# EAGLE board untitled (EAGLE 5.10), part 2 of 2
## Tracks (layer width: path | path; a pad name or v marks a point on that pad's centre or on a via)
+5V  (via drill 0.6 pad 1.78)  (4 unrouted)
  Top 0.254: v109.6,55.4 109.6,47.6
  Bottom 0.406: 126.8,57.4 126.8,53
  Bottom 0.61: 135.8,47.66 135.8,48.6 134.8,49.6 126.8,49.6 | 126.8,49.6 125.6,49.6 | 126.8,53 126.8,50.8 | 126.8,50.8 126.8,49.6 | 126.8,50.8 125.6,49.6 | 126.8,50.8 127.8,49.8 127.4,49.8 127.2,50 126.4,50 | 125.6,49.6 110.8,49.6 109.6,48.4
  Bottom 0.813: 135.8,47.66 U1.7 135.8,47.52 135.8,44 138.8,41 141.4,41 144.2,38.2 144.2,35.6 143.3,34.7 141.2,34.7 | 109.6,48.4 109.6,48 | L1.1 124.59,59.61 126.8,57.4 | 115.8,29.6 109.2,36.2 109.2,47.2 109.6,47.6 | 115.8,29.6 116.1,29.3 | STER..10 129.14,38.86 132.4,35.6 136,35.6 | 136,35.6 140.3,35.6 141.2,34.7 | 117.8,28.4 118.6,27.6 118.4,27.6 | WYS..1 134.8,10.59 134.8,16.2 141.7,23.1 | 116.1,29.3 116.2,29.2 | 116.2,29.2 117.8,27.6 118.4,27.6 | P1*.A 116.1,28.38 116.1,29.3 | R6*.2 118.4,28.6 117.8,29.2 116.2,29.2 | 117,28.8 117.6,28.8 118,28.4 117,28.4 115.8,29.6 | 115.8,29.6 117.4,29.6 118.8,28.2 118.8,28 118.4,27.6 | 118.4,27.6 117,27.6 116.4,28.2 | 145.83,26.97 146.6,27.75 146.6,29.8 144.4,32 | 145.83,26.97 PIEZO1.+ | 141.2,34.7 143,33.4 | 143,33.4 143.2,33.2 | 143.6,24.6 145.83,26.83 145.83,26.97 | 142.8,23.8 143.6,24.6 | 143,33.4 143,34.6 | 143,33.4 143,34.2 144.2,35.4 144.2,32.2 144.4,32 | 143.2,33.2 144.4,32 | 143.2,33.2 143.6,33.2 143.8,33.4 143.8,33.8 143.6,34 | 136,35.6 138,33.6 138,31.2 138.8,30.4 140.8,30.4 142.8,28.4 142.8,23.8 | 142.8,23.8 142.8,24 145.4,26.6 | 145.2,26.6 145.2,27.2 146,28 146,29.6 140.6,35 137.4,35 137.4,34.8 138.4,33.8 138.4,34.2 138.6,34.4 144,34.4 146.6,31.8 148.2,31.8 151.2,28.8 151.2,24.2 150.12,23.12 149.8,23.12 | 149.8,23.12 144.2,23.12 144.2,23.6 145,24.4 | 150.4,25.8 150.2,25.6 150.2,24 149.8,23.6 149.8,23.12 | 143.6,24.6 143.2,24.6 141.7,23.1 | 141.7,23.1 145.2,23.1 | 141.7,23.1 142.2,23.6 143.3,23.6 143.4,23.7 146.1,23.7 | 51.6,100.4 52.8,101.6 61.4,101.6 60.6,100.8 52.6,100.8 52.8,101 61.6,101 62.6,102 62.6,102.8 65.2,100.2 67.6,100.2 | 64.2,100.2 63,101.4 63,101.8 62.2,101 62.2,100.8 62.4,101 63,101
  Bottom 1.016: 98.2,134 98,133.6 98.4,134 103.8,134 108.4,138.6 108.4,144.2 109.2,145 121.6,145 124.06,142.54 124.06,142 U4.1 | v109.6,55.4 109.4,55.8 110.4,56.8 110.4,71.4 81.4,100.2 67.6,100.2 64.2,100.2 50.4,100.2 35,100.2 25.8,109.4 25.8,142.2 31.8,148.2 42.2,148.2 52.4,158.4 70.6,158.4 71.8,157.2 71.8,148.2 76.4,143.6 83.4,143.6 86.2,140.8 88.6,140.8 89.6,139.8 89.6,133.6 | 60.74,110.26 61,110 | 60.74,110.26 7805.OUT | 60.2,101.56 C5.2 | 60.2,101.56 60.64,101.56 C13.+ | 60.74,110.26 61.14,110.26 62.6,108.8 62.6,102.8 62.6,102.4 61.8,101.6 61.4,101.6 60.24,101.6 60.2,101.56
  Bottom 2.184: 143.6,24.6 144.4,24.8 145,24.8 | 146.2,24.6 145.2,25.4 145,24.4 145.8,25.2 147,25.2 147.8,24.8 148.6,25.2 149.8,26.4 147.2,24.4 147,24.2 148.8,24.2 | 150.4,25.8 150.4,28.6 148.4,28.6 146.6,26.8 148,26.8 148.6,26.2 148.6,27 148.8,27.2 148.8,29.8 147.8,30.8 147.8,30.4 147,29.6 147,30.2 144.8,32.4 142,32.4 141,33.4 139,33.4 139,31.8 139.4,31.4 142.6,31.4 144.8,29.2 144.8,28.4 144.6,28.2 144.4,28.2 | 144.4,28.2 142.2,30.4 | 144.4,28.2 144.8,27.8 144.8,27.2 143.8,26.2 143.8,27.6
+12V  (via drill 0.5 pad 3.81, 0.6 pad 2.18, 0.6 pad 2.54)  (1 unrouted)
  Top 0.254: v77.5,150.3 v66,150.3
  Bottom 0.406: 142.6,123.4 142.2,123.4 142.2,123.6 | 139.6,121.6 139.4,121.6 139.4,121.4 | 143.4,122.2 142.6,122.2 | 144.2,121.6 144.4,121.6 144.4,121.4
  Bottom 1.016: 110.5,164 112.1,165.6 112.1,169.8 113,170.5 v113,170.6 D2.C 113.69,170.69 117.4,174.4 117.4,186.8 116,188.2 v115.2,188.2 PK2.2 | 110.5,164 103.5,164 100,160.5 91,160.5 85,154.5 85,149.5 83.5,148 79.1,148 77.5,149.6 v77.5,150.3 77.5,157 82,161.5 82,164 80,166 76,166 71.5,161.5 58,161.5 56.5,163 56.5,169.5 55,171 47,171 39.7,163.7 39.7,163.49 D1.C 39.4,159.8 38,158.4 28,158.4 26.79,159.61 PK1.1 | 110.5,164 110.5,159.4 109,157.9 103.5,157.9 101.4,155.8 97,155.8 96.5,155.3 | 741.7 125.6,107.64 125.6,108.3 128.5,111.2 128.5,116.5 130,118 136,118 139.4,121.4 | v151.4,88.6 148.8,86 138.4,86 136.8,84.4 129,84.4 127.97,83.37 U741.7 128,82.26 128,79.6 | 156.6,89.2 156.2,88.8 | 156.6,89.2 156.8,89.4 | X8.2 X9.2 X10.2 138.2,78 136.6,79.6 128,79.6 | D3.C 126.79,78.19 128,79.4 128,79.6 | 143.4,125.4 143.4,142.4 139.2,146.6 130,146.6 128,148.6 122.8,148.6 121.4,147.2 109,147.2 106.8,145 106.8,139.2 103.8,136.2 95.6,136.2 | 143.4,125.4 143.4,122.2 143.4,122 | 144.4,121.4 148.4,117.4 156.6,117.4 158,116 158,90.6 156.6,89.2 | 96.5,155.3 95.7,154.5 | 143.4,125.4 139.6,121.6 | 143.4,125.4 143.4,122.4 144.2,121.6 | 142.6,122.2 142.6,123.4 142.8,123.6 | 142.2,123.6 142.8,124.2 | 110.21,140.81 LM358.8 110.2,138 106.2,134 106.2,128 104.8,126.6 104.8,109.4 103.4,108 100.2,108 99,109.2 99,112.8 101.2,115 101.2,118.8 98.8,121.2 98.8,127.4 95.6,130.6 95.6,136.2 | 95.6,136.2 95.6,154.4 96.5,155.3 | 66.88,150.32 66.68,150.22 66.66,150.2 66,150.2 | 60.84,125.56 7812.OUT | 60.84,125.56 61.24,125.56 | v66,150.3 66,150.2 | 60.84,125.56 61.64,125.56 63,124.2 63,119 61.8,117.8 60.32,117.8 C14.+ 60.12,118 54.6,118 v53.8,117.2 C9.1 55.16,115.8 62.8,115.8 64.8,117.8 64.8,129.4 68.2,132.8 68.2,143.6 66,145.8 66,150.2
-5V  (via drill 0.6 pad 2.18)  (1 unrouted)
  Top 0.254: v95.4,93.6 v114,93.6
  Bottom 1.016: 145.1,93.8 145,93.89 | 145.1,93.8 131.1,93.8 130.71,93.91 | 130.71,93.91 741.4 | 145.1,93.8 145.28,93.8 P1.S P2.S | 122.8,89.8 122.89,89.89 122.89,93.71 122.8,93.8 | 122.8,93.8 130.6,93.8 130.71,93.91 | LM723.7 89.12,126.12 88.2,125.2 88.2,118.2 86,116 86,108.2 | 86,108.2 86,105.6 86.4,105.2 | 86.4,105.2 91.6,100 91.6,95.8 93.8,93.6 v95.4,93.6 | 122.8,93.8 114.2,93.8 v114,93.6 | C7.2 77.14,119.6 74.8,119.6 | 84.6,108.2 81.8,108.2 80.6,109.4 80.6,111.6 78.8,113.4 76.8,113.4 74.6,115.6 74.6,119.4 74.8,119.6 | 84.6,108.2 86,108.2 | 7905.OUT 76.66,130.66 76.6,130.6 77.42,130.8 | 74.8,119.6 74.6,119.6 74.6,129.4 75.5,130.3 | 75.5,130.3 76,130.8 v77.4,130.6 77.42,130.8 | 77.42,130.8 C12.- | 86.4,105.2 83.6,108 84.8,108 85.4,107.4 85.4,107 | 84.6,108.2 84.8,108.2 85.8,109.2 | 76.7,131.6 76.7,131.5 75.5,130.3
D5
  Bottom 1.016: +.MP 114.2,161 114,160.8
  Bottom 2.54: 115.1,161.9 114,160.8 113.6,160.4 113.6,158.8 110.4,155.6 105.2,155.6 104.8,155.4 99.11,149.89 | 99.11,149.89 98.7,149.5 | D5.C 98.56,149.35 99.11,149.89
  Bottom 3.81: PK2.O1 124.79,188.19 122.6,186 122.6,185.1 122.5,185 122.6,184.9 122.6,180.6 125,178.2 125,167 121.2,163.2 116.6,163.2 116.2,162.8 116,162.8 115.1,161.9 114.2,161
E1  (via drill 0.5 pad 3.81)
  Bottom 1.016: T3.1 104.13,197.23 105.9,199 150.8,199 154.5,195.3 154.5,163 T6.3 133,161.5 131.5,160 131.5,156.5 133.5,154.5 142.5,154.5 153,144 v153,134.03 T5.3
GND  (via drill 0.6, 0.6 pad 1.78, 0.6 pad 2.18, 0.6 pad 2.54)  (4 unrouted)
  Top 0.254: v136.8,15.5 v129.4,15.5 | v95.4,90.4 112.6,90.4 v112.8,90.6 | v69.4,155 v81.6,155 | v121.8,138.6 121.8,133 122,132.8 | 122,132.8 | 122,132.8 121.6,132.8
  Top 0.305: v156.2,47.6 156.2,55
  Top 0.406: 122,132.8 R2.1
  Bottom 0.254: v81.6,155 81.67,153.94
  Bottom 0.61: U1.8 138.27,48.87 139,49.6 155.4,49.6 156.2,48.8 v156.2,47.6 | U1.22 135.73,54.07 136.6,53.2 155.4,53.2 156.2,54 156.2,55 | 67.6,103 67.7,105.4 64.2,105.2 | 136.4,29.8 136.4,29.7 137.4,28.7 136.5,27.8
  Bottom 0.813: U1.22 135.8,55.28 135.8,57.2 134.66,58.34 C2*.1 C1*.1 134.66,58.86 v134.6,58.8 131.4,58.8 130.2,60 130.2,71.1 | T4.1 128.31,73.29 130.2,71.4 130.2,71.2 | WYS..2 134.93,7.93 136.8,9.8 v136.8,15.5 143.1,21.8 150.8,21.8 152.8,23.8 152.8,29.4 149,33.2 147.4,33.2 146.4,34.2 146.4,38 142,42.4 139.8,42.4 138.27,43.93 U1.8 | 126,75.4 126,75.3 130.2,71.1 | 130.2,71.2 130.2,71.1 | 130.2,71.2 127.2,74.2 127.7,74.2 127.8,74.3 | 66.4,104 68,105.8 | 87,99 86.3,98.3 86.2,98.2 | 64.6,111.6 64.2,111.2 64.2,105.2 64.2,103.8 65.8,102.2 | 81.6,102.2 86.6,97.4 86.6,98.4 86.7,102.7 | 65.7,103.9 66,102.9 | T3*.E 126.4,23.47 126.2,23.27 126.2,22.6 127.4,21.4 132.2,21.4 133.44,22.64 | 133.6,23.57 T2*.E 133.44,22.64 | T1*.E 134.13,33.8 135,33.8 136.4,32.4 136.4,29.8 136.4,28.8 | 136.4,28.8 136.4,25.6 133.44,22.64 | 111.2,25.6 115.8,25.6 122.8,18.6 135,18.6 141.2,24.8 141.2,27.6 140,28.8 136.4,28.8 | v129.4,15.5 129.2,15.8 121.6,15.8 116.2,21.2 112.2,21.2 111.2,22.2 111.2,25.6 | P1*.E 111.2,28.2 111.2,25.6
  Bottom 1.016: 48,177 43.54,178.94 T1.E | 110.37,171.77 110.37,166.77 109.1,165.5 103,165.5 99.5,162 88.5,162 88.09,162.41 | 110.37,171.77 110.37,172.36 | 110.37,171.77 110.9,172.3 | 110.9,172.3 111.8,173.2 113.8,173.2 115.8,175.2 115.8,181.6 111.6,185.8 111.6,190.4 113.4,192.2 142.6,192.2 143.8,191 143.8,185 142.8,184 v139.2,184 | 118.79,132.99 118.98,132.79 R2.1 | 118.79,132.99 117.27,131.47 C18.- | 98,91.8 98,91.6 96.8,90.4 | 98,92.2 98,94.6 96.6,96 94.6,96 93.2,97.4 93.2,100.6 87.5,106.3 87.5,114.2 89.3,116 91.27,116 LM723.3 | v95.4,90.4 95,90.3 | v95.4,90.4 96.8,90.4 | 92,165 91.5,165 91.5,165.19 C4.- | T4.1 126.47,74.93 126,75.4 123.4,78 115,78 110.8,82.2 110.8,90.6 | 110.8,90.6 v112.8,90.6 114,90.6 115,89.6 115,85.6 115.6,85 117.23,85 C17.- | 132,143.4 138,143.4 140.2,141.2 140.2,126.6 134.8,121.2 128.2,121.2 124.6,117.6 124.6,113.81 R9.2 124.49,112.49 123.4,111.4 116.6,111.4 114.4,109.2 114.4,97.2 110.8,93.6 110.8,90.6 | 132,143.4 129.4,140.8 | 129.4,140.8 129.2,140.6 | 129.2,140.6 129.2,139.2 128,138 122.8,138 122.2,138.6 v121.8,138.6 | LM358.4 117.81,133.97 118.79,132.99 | C10.2 86,170.2 85.9,170.1 | U4.3 129.34,140.86 129.4,140.8 | T2.E 110.74,172.46 110.9,172.3 | TR1.8 TR1.11 | TR1.8 35.8,118.51 35.8,133.6 33.6,133.6 31.4,135.8 31.4,142.4 35.6,146.6 | 35.6,146.6 42.8,146.6 53,156.8 67.6,156.8 v69.4,155 | TR1.8 35.66,118.4 32.2,118.4 31,117.2 31,112 33.4,109.6 38.8,109.6 41,111.8 41,140.8 42,141.8 45.2,141.8 45.6,142.2 | 58.2,135.8 55.2,135.8 C2^444.- | 58.2,135.8 62.2,135.8 C1.+ | 58.2,135.8 58.3,135.7 58.3,135.4 | 58.3,135.4 7812.GND 58.3,123.6 58.3,122.34 58.2,122.24 59.04,122.24 C14.-
  Bottom 1.016: v69.4,155 68.6,155.8 | v69.4,155 70.2,154.2 70.2,147.6 75.06,142.54 75.6,142 80.2,142 81.8,140.4 81.8,137.7 7905.GND | 58.6,143.2 58.6,149.2 57.2,150.6 54,150.6 45.6,142.2 | 58.6,143.2 59.76,143.2 C6.1 | 58.6,143.2 57.4,143.2 57.24,143.04 C8.2 58.4,143 58.6,143.2 | 58.6,143.2 58.6,135.7 58.3,135.4 | 58.4,106.6 58.2,106.8 58.2,108.2 7805.GND 58.2,112.4 | 58.4,106.6 54.84,106.6 C5.1 | 58.4,106.6 60.28,106.6 C13.- | 54,113.4 53.68,113.61 52.2,114.6 | 52.2,121 53.8,122.4 54.64,122.4 | 7905.GND 81.74,131.36 C12.+ | 77.66,124.74 C7.1 v77.6,124.6 78.8,124.6 79.6,125.4 79.6,128.4 81.8,130.6 81.8,137.58 7905.GND | v95.4,90.4 94.8,90.4 90,95.2 90,99.4 86.7,102.7 84.6,104.8 82,104.8 80.2,106.6 | 77.54,110.6 C15.2 v77.6,110.6 77.6,109.2 77.7,109.1 | 129.2,142.4 129.2,140.6 | 129.2,142.4 129.2,143 | 132,143.4 130.2,143.4 129.2,142.4 | 129.2,142.4 130.2,142.4 130.6,142.8 | 35.6,146.6 32.4,146.6 27.4,141.6 27.4,110.2 35.3,102.3 49.8,102.3 51.2,103.7 51.2,106 47,110.2 | 89.2,99 89.4,99 89.4,97 88.6,97 88.6,97.6 89,97.6 89,95 94.6,89.4 95.8,89.4 96.8,90.4 | 96.8,90.4 96.8,90.6 98,91.8 | 98,91.8 98,92.2 | 98,92.2 97.8,92.2 96.8,91.2 93.6,91.2 89.2,95.6 | 73.2,113.6 73.2,113.2 74.9,111.5 | 67.6,110.2 67.6,116.4 66.6,117.4 | 66.6,117.4 66.6,117.2 | 66.6,117.2 63.6,114.2 64.2,114.2 66.8,116.8 66.8,117 66.6,117.2 | 66.6,117.4 66.6,128.8 70,132.2 70,142.6 70.2,142.6 74.2,138.6 74.2,131.6 72.8,130.2 72.8,114.8 74,113.6 70.8,113.6 68.4,111.2 68.6,111.2 69,110.8 69.4,111.2 69.4,111.4 66,114.8 65.6,114.8 65.4,114.6 65.6,114.6 67,116 67,114.6 | 45.6,142.2 45.6,111.6 47,110.2 | 47,110.2 47,109 46.8,108.8
  Bottom 1.016: 86.6,98.4 86.4,98.4 86.3,98.3
  Bottom 1.27: 81,173 v81,177.4
  Bottom 2.184: 57.2,142.8 59.8,142.8 59.8,138.2 62.2,135.8 55.2,135.8 55.2,141.4 58.4,144.6 59.6,144.6 62.4,141.8 62.4,139.4 | 62.4,139.4 60.2,141.6 60.2,139.6 61.4,138.4 60.4,138.4 58.8,136.8 56.6,136.8 56.4,137 56.4,140.4 57.6,141.6 57.6,138.4 57.8,138.2 55.2,135.6 55.2,131.4 58.4,128.2 62.4,132.2 62.4,139.4 | 57.2,134.2 56.6,133.6 56.6,131.8 56.8,131.6 59.8,131.6 60.8,132.6 60.8,133.8 60.4,134.2 59.8,134.2 58.4,132.8 58.4,123.6 | 58.4,123.6 58.4,123.28 C14.- 59.72,121 | 52.2,121 51.2,120 51.2,116.09 53.68,113.61 53.69,113.6 57.4,113.6 | 52.2,121 53.44,122.24 | C9.2 56.94,122.24 58.3,123.6 | 52.2,121 60.8,121 60.8,121.2 58.4,123.6 | C5.1 59.56,106.64 60.4,105.8 60.4,105.2 54.8,105.2 53.8,106.2 53.8,106.6 56.6,106.6 58,108 | 58.2,108.2 60.4,106 60,106 58,108 | 58.2,108.2 58,108 | 58.2,108.2 58.2,112.8 57.4,113.6 | 57.4,113.6 72.4,113.6 73,113 68.2,113 | 68.2,113 63.2,113 | 63.2,113 62.8,113.4 | 63.2,113 64.6,111.6 65,111.2 65.2,104.2 65.23,104.2 65.43,104 | 89.2,99 88.8,99 84,103.8 84,104.6 82.6,106 80.8,106 80.2,106.6 77.7,109.1 77.54,109.26 | 77.54,109.26 77.54,110.6 | 75.4,111 74.9,111.5 72.8,113.6 68.6,113.6 66.4,111.4 66,104.3 67.6,103 | 82.2,104.2 85.6,100.8 82.9,103.2 82.2,104.2 | 65.5,103.5 68.8,112.4 69.6,112.2 | 67.6,110.2 67.3,104.9 66.4,104 | 66.4,104 66.1,103.7 | 65.43,104 65.5,103.5 | 65.43,104 65.4,104.2 | 69.2,109.4 67,110.2 69.2,110.8 65.76,104.02 | 65.5,103.5 65.76,104.02 | 66.2,110.2 67,109.4 68,110.6 68,105.6 69,105.6 69.6,105 69.6,107.8 69.4,108 70,108 70.6,107.4 70.6,111 70.8,111.2 70.8,109.6 71.6,108.8 71.6,110.6 | 69.4,103.6 65,106.6 68.2,107.6 68.8,105.8 66.4,104
  Bottom 2.184: 66.4,104 70,103 | 67,114.6 68.2,114.6 69.2,115.6 71.4,115.6 71.8,115.2 71.8,130.8 72,131 72,131.6 72.8,132.4 72.8,138.6 70.8,140.6 70.8,131.6 67.6,128.4 69.6,128.4 70.6,129.4 70.6,122.8 70.2,122.4 70.2,124 67.4,126.8 69.2,126.8 69.4,127 69.4,117.4 70.6,116.2 70.6,122.2 67.6,125.2 67.6,116.6 68.2,116 68.2,113 | 71.6,110.6 71.6,111.6 | 71.6,110.6 72.8,109.4 72.8,111 73,111.2 74.4,109.8 74.4,112.4 | 74.4,112.4 72.6,114.2 | 74.4,112.4 76.8,110 76,110 75.6,109.6 77.2,109.6 77.54,109.26 | 82.2,104.2 81.4,104.2 79.8,105.8 79.8,103.2 79.4,102.8 82,102.8 89.2,95.6 | 65.7,103.9 65.7,103.96 65.76,104.02
  Bottom 3.81: 91.19,170 C3.- | 91.19,170 86,170 85.9,170.1 83,173 81,173 76,173 74,171 74,169 70.8,166 69.8,165 63,165 61,167 61,173 57,177 48,177 47.2,177 42.89,181.31 PK1.P1 | R12.1 81.67,153.94 81.67,155.97 88.09,162.41 C4.- 91.19,170
N$1  (via drill 0.8 pad 6.45)
  other vias: 148,195
N$2  (via drill 0.8 pad 6.45)
  other vias: 8,195
N$3  (via drill 0.6 pad 1.78)
  Bottom 0.813: U1.20 140.81,57.01 141.8,58 141.8,60.6 140.4,62 v139.8,62 C1*.2 137.94,63.8 133.8,63.8 132.21,62.21 L1.2
N$4
  Top 0.254: 71.14,41.13 0.07,41.13 0.16,0.08 71.23,0.08 71.14,41.13
N$5  (via drill 0.8 pad 6.45)
  other vias: 143,169
N$6  (via drill 0.8 pad 6.45)
  other vias: 118.6,169
N$7  (via drill 0.8 pad 6.45)
  other vias: 119,116
N$8  (via drill 0.8 pad 6.45)
  other vias: 142,116
N$9
  Bottom 3.81: 14.8,170.4 AC_12V.2 | 14.8,170.4 AC-12V.1 | PK1.O1 34.41,175.21 29.8,170.6 15,170.6 14.8,170.4
N$10
  Bottom 3.81: PK1.S1 47.79,186.39 B1.-
N$11
  Bottom 1.016: R10.2 103.69,160.19 100.9,157.4 96.2,157.4 94,155.2 94,130.6 91.6,128.2 87.2,128.2 86.2,127.2 86.2,122 85.24,121.04 LM723.10
N$12
  Bottom 3.81: ~240V.1 11.52,190.12 3,181.6 3,161.8 10.2,154.6 14.79,154.6 TOROID.2
N$13
  Bottom 3.81: ~240V.2 13.29,185.09 8.6,180.4 8.6,163.6 12.6,159.6 14.79,159.6 TOROID.1
N$14
  Bottom 1.016: T3.3 104.13,171.67 105,170.8 R10.1
N$15
  Bottom 1.016: D1.A 38.46,171.75 T1.C 38.2,174.47 38.2,170.6 37.2,169.6 37.2,162.2 35.99,160.99 PK1.2
N$16
  Top 0.813: W1.2 91.61,3.97 91.05,4.53 91.05,7.53 89.85,8.73 88.93,8.73 SV2.1 86.28,6.26 86.25,2.73 84.85,1.33 76.45,1.33 72.45,5.33 72.45,14.93 79.45,21.93 86.85,21.93 87.85,22.93 87.85,33.93 90.91,36.99 W1.15
N$17  (via drill 0.6 pad 2.54)
  other vias: 88.6,145.2
N$18  (via drill 0.8 pad 3.81)
  other vias: 32.5,198.8
N$19  (via drill 0.8 pad 3.81)
  other vias: 28,198.8
N$20
  Bottom 3.81: B1.AC1 69.31,189.69 69.1,189.9 | 69.1,189.9 68.5,190.5 | 69.1,189.9 66.2,192.8 24.4,192.8 21.2,189.6 21.2,183.2 17.91,179.91 AC_12V.1
N$21
  Bottom 3.81: B1.AC2 51.1,164.8 49.6,164.8 40,155.2 26.2,155.2 21.8,159.6 21.8,162.8 19.91,164.69 AC-12V.2
N$22
  Bottom 1.016: T1.B 41.2,173.2 42.6,171.8 R1.1
N$23
  Bottom 2.54: R18.1 127.4,157.26 127.4,156.8 127.2,157 127.2,157.4 127.4,157.6 127,157.6 127.3,157.3 127.3,156.1
  Bottom 3.81: T5.1 150,124 148,126 148,144.5 141.1,151.4 132,151.4 127.3,156.1
N$25  (via drill 0.6 pad 2.18)
  Top 0.254: v78,162.6 v78,168.2
  Bottom 1.016: D4^.C R11.2 v78,168.2 | LM723.12 LM723.11 83.59,118.6 82.2,118.6 81.4,119.4 81.4,127.4 83.6,129.6 91,129.6 92.2,130.8 92.2,140.2 90,142.4 86.8,142.4 84.2,145 77.2,145 73.4,148.8 73.4,158 v78,162.6
N$26
  Bottom 0.61: 118.8,56.2 118.8,53.4 118,52.6 108,52.6 106.6,54 106.6,57.4
  Bottom 0.813: U1.26 125.57,56.23 124.4,57.4 119.4,57.4 118.8,56.8 118.8,56.2
  Bottom 1.016: 106.6,57.4 106.6,70.6 80.2,97 33.6,97 22.2,108.6 22.2,143.2 30.8,151.8 41.4,151.8 51,161.4 53.2,161.4 54.8,163 54.8,168.6 54,169.4 48,169.4 42.6,164 R1.2
N$27
  Bottom 0.813: U1.21 138.27,57.33 C2*.2
N$28  (1 unrouted)
  Bottom 3.81: T6.1 150,151.5 143.5,158 135.53,158
N$29
  Bottom 0.254: 71.4,0 100.6,0 100.6,41 71.4,41 71.4,0
N$30  (via drill 0.6 pad 2.54)
  Top 0.254: v124.3,146.2 v124.3,151
  Bottom 0.813: 132,173.4 130.4,171.8 130.4,166.4 122.2,158.2 122.2,151.6 | 119.86,150.6 C11.2
  Bottom 1.016: 128.65,119.15 127,117.5 127,112 124.8,109.8 117.6,109.8 116.6,108.8 116.6,98 119.1,95.5 126.5,95.5 128.2,97.2 128.2,99.96 741.3 | 128.65,119.15 129,119.5 | v124.3,146.2 124.3,146 128.4,146 129.4,145 138.6,145 141.8,141.8 141.8,126 135.4,119.6 129.1,119.6 128.65,119.15 | 132,173.4 135,176.4 142.67,176.4 C16.- | R13.1 103.8,141.4 D5.A | -.MP 114.6,151.2 114.8,151.4 | R12.2 108.72,151 109,151.28
  Bottom 2.54: 108.89,151.28 109,151.28 113.6,151.28 113.72,151.4 114.8,151.4 119,151.4 119.74,150.66 C11.2 | 122.2,151.6 123.7,151.6 123.95,151.35 | v124.3,151 123.95,151.35 | 119.86,150.6 119.86,150.94 119.4,151.4 123.9,151.4 123.95,151.35 | R12.2 108.33,150.74 103.6,146 103.6,143 D5.A
N$31
  Bottom 0.254: 71.27,0.08 0.27,0.08
N$32
  Bottom 1.016: R4.2 108,170.4 106.8,171.6 106.8,174.2 107.6,175 T2.B
N$33  (via drill 0.6 pad 2.54)
  Bottom 1.016: 109.27,181 109.27,194.27 111,196 115.38,196 PK2.1 | D2.A v113,178.4 113,180 112,181 109.27,181 | 109.27,181 109.27,177.6 T2.C
N$34  (via drill 0.6 pad 2.54)
  Bottom 0.813: 131.8,175.8 129,173 129,166.8 119.8,157.6 v119.8,155.8 C11.1 119.74,155.8 114.2,155.8 111.8,153.4 106.6,153.4 101,147.4 R15^.2
  Bottom 1.016: 135.5,187.51 135.51,187.5 | 131.8,175.8 135.8,179.8 | 135.8,179.8 135.8,184.2 135.4,184.6 | 135.8,179.8 142.07,179.8 142.34,179.53 | 142.34,179.53 C16.+ | R5.2 143.21,180.41 142.34,179.53
  Bottom 2.54: R18.2 127.47,184.03 128.5,183
  Bottom 3.81: 135.51,187.5 PK2.P1 | 128.5,183 134.37,183 R19.2 135.4,184.6 135.4,186.9 135.5,187 135.5,187.51
N$35
  Bottom 1.016: TR1.7 38.1,113.5 39.2,114.6 39.2,141.6 41,143.4 44.4,143.4 53.8,152.8 56.12,152.8 B2.AC1
N$36
  Bottom 1.016: 148.4,55.24 U1.17 148.43,62.17 142.8,67.8 142.8,71.81 R7.2
N$37  (via drill 0.8 pad 2.18)
  other vias: 78,169.7
N$38  (via drill 0.6 pad 2.18)
  Bottom 1.016: TR1.12 35.77,142.37 38.4,145 43.6,145 53.8,155.2 58,155.2 58.8,154.4 58.8,151.6 61.2,149.2 v61.2,147.8 B2.AC2
N$39  (via drill 0.8 pad 6.45)
  other vias: 8,101
N$40  (via drill 0.6 pad 6.45)
  other vias: 112.8,10.5
N$41  (via drill 0.6 pad 2.18)
  other vias: 60.2,118
N$42
  Bottom 1.016: 45.2,175.6 49,175.6 | 45.2,175.6 43.6,175.6 | 43.6,175.6 43.6,174.6 | 43.6,175.6 43.6,177.2 45,177.2 45,176.2 44.2,176.2 44.2,176.6 | 45.2,175.6 43.6,174
N$43  (via drill 0.6 pad 2.18)
  other vias: 56.2,152.8
N$44  (via drill 0.6 pad 2.54)
  other vias: 86,172
N$45  (via drill 0.6 pad 2.54)
  other vias: 86,177
N$46  (via drill 0.6 pad 2.54)
  other vias: 81,169.6
N$47  (via drill 0.6 pad 6.45)
  other vias: 147.4,10.5
N$48  (via drill 0.6 pad 2.54)
  other vias: 108,167.8
N$49  (via drill 0.6 pad 2.54)  (2 unrouted)
  other vias: 105,167.8 105,160.2 108,160.2
N$50  (via drill 0.6 pad 2.18)
  other vias: 61.2,152.8
N$51  (via drill 0.6 pad 2.54)
  other vias: 42.6,170.8
N$52  (via drill 0.6 pad 2.54)  (2 unrouted)
  other vias: 39.4,170.8 39.4,163.2 42.6,163.2
N$53  (via drill 0.6 pad 6.45)
  other vias: 67.13,36.58
N$54  (via drill 0.6 pad 2.18)
  Bottom 1.016: B2.+ 53.76,147.76 50.6,144.6 | 52.2,143.04 C8.1 52.16,143.04 50.6,144.6 | 50.6,144.6 47.6,141.6 47.6,136.2 | 47.6,136.2 47.6,126.2 | 47.6,126.2 47.6,112.2 49.4,110.4 55.6,110.4 7805.IN | 7812.IN 47.64,126.16 47.6,126.2 | C2^444.+ 51.6,135.8 48,135.8 47.6,136.2
  Bottom 2.184: v56.2,147.8 56.2,147 51.6,142.4 | 51.6,142.4 51.4,142.2 | 51.6,142.4 51.6,135.8 51.6,129.8 55.2,126.2 53.4,126.2 48.4,121.2 48.4,114.6 52.4,110.6 | 52.4,110.6 55.2,110.6 | 52.4,110.6 50,110.6 49.8,110.8 49.8,111 48.2,112.6 48.2,123 52.4,127.2 50.8,127.2 48.6,125 48.6,126.6 50.8,128.8 50.8,142.2 50.4,142.6 50.4,142.8 54.4,146.8 54.2,146.8 48.4,141 48.4,128.8 49,128.2 49,140.4 50.2,141.6
N$55
  Bottom 2.184: 33.8,145.8 33.2,145.8 28.4,141 28.4,110.8 35.9,103.5 50.1,103.7 47.7,104.5 50,105.5 45,110.4 45,140.8 42.8,140.8 41.6,139.6 41.6,111 39,108.4 33.2,108.4 30,111.6 | 30,111.6 29.8,111.8 29.8,141.4 30.4,142 30.4,119.4 31.2,118.6 31.2,118.8 32.4,120 34.6,120 34.8,119.8 34.8,131 31.4,134.4 31.4,121.6 32.2,120.8 33,120.8 33.8,121.6 33.8,130.4 32.8,131.4 32.8,122.6 32.4,122.2 32.4,118.4 30,116 30,111.6 | 30,111.6 37.6,104.2 45.8,105.4 48.4,104.8 48.6,105.2 43.4,110.4 43.4,139.6 43.6,139.8 43.6,111 38.4,105.8 37.6,105.8 36.2,107.2 42.6,107.2 43.6,108.2 47,104.8 44.7,105.9 38.9,105.9 38.6,106.5 39,105 40.2,105 41.2,106 43.6,106 43.8,105.8 44.2,105.8 45.6,104.4 41.8,104.4 41.6,104.2
N$56  (via drill 0.6 pad 2.18)
  other vias: 60.2,121.4
N$57  (via drill 0.6 pad 6.45)  (1 unrouted)
  other vias: 67.33,4.38 67.13,4.38
N$58  (via drill 0.6 pad 6.45)
  other vias: 7.63,36.58
N$62
  Bottom 1.016: 7905.IN 79.2,139.4 78.2,140.4 75,140.4 68.6,146.8 68.6,152 67.8,152.8 67.8,152.84 63.2,152.84 | 63.2,152.84 B2.- | 63.4,151.4 63.4,152.64 63.2,152.84 | 61.4,152.8 62,152.8 63.4,151.4 | 63.4,151.4 64.8,152.8 | 63.4,146.9 63.4,145.8 65,144.2 | 63.4,146.9 63.4,151.4 | 65,144 65,143.04 C6.2 65.04,143.96 65,144 | 65,144.2 65,144 | 65,144.2 65.8,143.4 65.78,143.38 C1.- 65.8,135.82 | 63.4,146.9 63.4,144.7
N$66  (via drill 0.6 pad 2.18)
  other vias: 53.8,101.6
N$67  (via drill 0.6 pad 2.18)
  other vias: 60.2,102
N$68  (via drill 0.6 pad 2.18)
  Bottom 1.016: v65.8,135.8 65.3,135.8 65.2,135.7 65.2,142.9 63.5,144.6 63.5,151.2
N$69  (via drill 0.6 pad 2.18)
  other vias: 65,143
N$71  (via drill 0.6 pad 2.18)
  other vias: 81,130.6
N$72  (via drill 0.6 pad 2.18)
  other vias: 77.6,119.4
N$73  (via drill 0.6 pad 2.18)
  other vias: 77.6,115.8
N$76
  Bottom 1.016: 83.47,113.2 LM723.13 83.67,113.4 82.6,113.4 80.26,115.74 C15.1
N$77
  Bottom 1.016: 741.5 131.79,107.61 136.6,102.8 137.66,102.8 P2.A
N$78
  Bottom 1.016: R9.1 132.3,113.7 132.3,110.3 134.2,108.4 137.66,108.4 P5.A 137.75,108.3
N$79
  Bottom 0.813: 741.2 125.63,101.23 126.6,102.2 132.8,102.2 135.4,99.6 140,99.6 143.2,102.8 147.2,102.8 149.6,100.4 152.2,100.4 153.4,101.6 153.4,106.8 152,108.2 150.56,108.2 P5.E 150.41,108.2 146.2,108.2 145.41,107.41 P5.S
  Bottom 1.016: 741.2 125.63,98.33 124.6,97.3 119.8,97.3 119.1,98 R8.1
N$80
  Bottom 0.406: 107.4,98.4 107.4,81.2 114.2,74.4
  Bottom 0.61: U1.24 130.65,53.45 132,52.1 155.9,52.1 158.2,54.4 158.2,55.6
  Bottom 0.813: 107.4,98.4 107.4,98.6 | 114,74.4 114.2,74.4 122.4,74.4 | 158.2,55.6 158.2,83.4 | 109.6,100.8 109.6,100.6 107.4,98.4 | 107.4,98.4 107.4,81 114,74.4 | 114,74.4 122.4,74.4 | 122.4,74.4 126.8,70 126.8,59.4 130.4,55.8 130.4,55.46 U1.24 130.6,55.26
  Bottom 1.016: R8.2 118.9,106 119.6,105.3 127.1,105.3 128.17,106.37 741.6 128.2,107.64 128.2,108.4 130,110.2 130,115.5 131,116.5 134.6,116.5 139.9,111.2 144.2,111.2 149,116 155.8,116 156.4,115.4 156.4,93 153.8,90.4 153.8,87.4 158.2,83.4 | R17.2 123.4,126.2 122.8,125.6 115.8,125.6 109.6,119.4 109.6,100.8 107.4,98.6
N$81  (via drill 0.6, 0.6 pad 2.18)
  Top 0.254: v95.4,98.2 v110.2,98.2 110.3,98.3
  Bottom 1.016: R2.2 R16.2 129,129.6 127.6,128.2 127.6,125.4 126.4,124.2 116.4,124.2 111.2,119 111.2,99.2 v110.2,98.2 | LM723.2 89.62,113.42 89,112.8 89,107 95.4,100.6 v95.4,98.2
N$82
  Bottom 0.813: 741.1 123.1,102.3 124.4,103.6 133.2,103.6 136,100.8 139.4,100.8 142.6,104 149.16,104 P2.E
  Bottom 1.016: 741.1
N$83  (via drill 0.6 pad 2.54)
  other vias: 119.1,107.1
N$84  (via drill 0.6 pad 2.54)
  other vias: 119.1,99.5
N$85  (via drill 0.6 pad 2.54)
  other vias: 132.4,113.8
N$86  (via drill 0.6 pad 2.54)
  other vias: 124.4,113.8
N$87
  Bottom 1.016: 150.4,96.39 P1.E 150.6,96.19 150.6,91.2 147,87.6 137.8,87.6 136.2,86 128.6,86 127,84.4 123.6,84.4 122.89,83.69 U741.5
N$88
  Bottom 0.813: 138.12,96.8 P1.A 137.91,96.6 142.2,96.6 143,97.4 143,100.8 143.8,101.6 146.8,101.6 148.6,99.8 148.6,98.8 147.6,97.8 147.6,95.8 148.6,94.8 148.6,91.3 146.5,89.2 137.2,89.2 135.6,87.6 131.2,87.6 130.51,88.29 U741.1
N$89  (via drill 0.6 pad 2.18)
  Top 0.254: v112.9,87.5 v100.4,87.5
  Bottom 1.016: U741.2 128,89.88 128,87.8 126.2,86 122.6,86 120.6,84 120.6,80.2 120.8,80 124.8,80 | 124.8,80 115.4,80 112.5,82.9 112.5,87.1 v112.9,87.5 | U741.6 125.43,80.63 124.8,80 | LM723.5 92.27,121.2 94.2,121.2 95.4,120 95.4,105 101.1,99.3 101.1,88.5 100.4,87.8 v100.4,87.5
N$90  (via drill 0.6 pad 2.54)
  other vias: 156.2,88.6
N$91
  Bottom 0.813: U741.3 125.43,91.23 126.4,92.2 133.8,92.2 134.8,91.2 R6.1
  Bottom 1.016: U741.3 125.43,88.63 124.4,87.6 117.43,87.6 C17.+
N$92
  Bottom 0.813: U1.2 123.03,43.5 STER..5
N$93  (via drill 0.6 pad 2.54)
  other vias: 134.8,90.2
N$94  (via drill 0.6 pad 2.54)
  other vias: 134.8,82
N$96
  Bottom 0.813: 125.8,76 128.2,76 128.6,75.6 126.3,75.6 126.2,75.7
N$97  (via drill 0.6 pad 2.54)
  other vias: 112.8,90.6
N$98  (via drill 0.6 pad 2.54)
  other vias: 95.4,90.4
N$99  (1 unrouted)
N$100
  Bottom 1.016: T4.3 134.07,74.93 135.2,73.8 135.2,72.01 R7.1
N$101
  Bottom 0.813: U1.3 125.57,43.5 STER..7
N$102
  Bottom 1.016: X8.3 X9.3 X10.3 139.14,75.4 137.2,75.4 134.6,78 D3.A 131.2,78 130.4,77.2 130.4,75.13 T4.2
N$105
  Bottom 0.813: 128.4,62 128.4,59.6 130.4,57.6 132.6,57.6 133.2,57
  Bottom 1.016: 116.1,121.7 112.8,118.4 112.8,97.8 109,94 109,81.6 114.4,76.2 122.8,76.2 128.4,70.8 128.4,62 | 116.1,121.7 117,122.6 | 116.1,121.7 117.2,122.8 134.2,122.8 138.6,127.2 138.6,140.6 137.4,141.8 132.8,141.8 131,140 131,138.4 129,136.4 120.6,136.4 119.6,137.4 119.6,140 120.4,140.8 122.6,140.8 123.8,139.6 126.2,139.6 126.8,140.2 U4.2 | 133.2,57 U1.23
N$106  (via drill 0.6 pad 2.54)
  other vias: 89.4,133.6
N$107  (via drill 0.6 pad 2.54)
  other vias: 98.4,133.6
N$108
  Bottom 1.016: R5.1 148.81,172.79 149.8,171.8 149.8,169.22 P4.A
N$109
  Bottom 1.016: R3.2 148.8,184 150,182.8 150,181.45 P4.E
N$110  (via drill 0.6 pad 2.54)
  other vias: 146.8,184
N$111
  Bottom 0.813: U1.4 128.11,43.5 STER..9
N$112  (via drill 0.6 pad 2.54)
  other vias: 119.8,150.6
N$113  (via drill 0.6 pad 2.54)
  other vias: 142.8,179.2
N$114  (via drill 0.6 pad 2.54)
  other vias: 142.8,176.2
N$115  (via drill 0.6 pad 2.54)
  other vias: 147,180.4
N$116  (via drill 0.6 pad 2.54)
  other vias: 147,172.8
N$117  (via drill 0.6 pad 2.18)
  other vias: 117.4,87.6
N$118  (via drill 0.6 pad 2.18)
  other vias: 117.4,84.8
N$119
  Bottom 0.813: U1.5 130.65,43.5 STER..11
N$120  (via drill 0.6 pad 2.18)
  Bottom 1.016: 112.73,131 112.73,130.67 114,129.4 v114.6,129.4 C18.+ | 112.73,131 LM358.2 | R14.1 112.72,131.01 112.73,131
N$121
  Bottom 1.016: LM358.3 115.27,135.87 116,136.6 118.4,136.6 120.2,134.8 129.6,134.8 130.4,135.6 132.8,135.6 133.8,134.6 133.8,127.2 132.8,126.2 R17.1
N$122
  Bottom 0.813: U1.6 133.19,43.5 STER..13
N$123
  Bottom 1.016: 113.6,127.2 113.2,127.2 | 113.6,127.2 118.4,127.2 120.8,129.6 R16.1 | LM358.1 108.79,133.99 107.8,133 107.8,127.2 | 107.8,127.2 113.6,127.2 | 107.8,127.2 106.4,125.8 106.4,102 104.2,99.8 104.2,79.8 114,70 123.6,70 124.4,69.2 124.4,67.4 123.4,66.4 115.6,66.4 114.5,65.3 R4*.1
N$124  (via drill 0.6 pad 2.18)
  other vias: 121.8,138.6
N$125  (via drill 0.6 pad 2.18)
  other vias: 121.8,132.8
N$126  (via drill 0.6 pad 2.18)
  other vias: 123.8,132.8
N$127  (via drill 0.6 pad 2.18)
  other vias: 131.4,132.8
N$128  (via drill 0.6 pad 2.18)
  other vias: 131.4,129.6
N$129  (via drill 0.6 pad 2.18)
  other vias: 123.8,129.6
N$130  (via drill 0.6 pad 2.18)
  other vias: 131.4,126.2
N$131  (via drill 0.6 pad 2.18)
  other vias: 123.8,126.2
N$132  (via drill 0.6 pad 2.18)
  other vias: 110.2,131
N$133  (via drill 0.6 pad 2.18)
  other vias: 110.2,123.4
N$134  (via drill 0.6 pad 2.18)
  other vias: 95.4,98.2
N$135  (via drill 0.6 pad 2.18)
  other vias: 110.2,98.2
N$136
  Bottom 0.813: 125.9,155.6 125.9,155.8 125.8,155.9 125.8,157.7 126.6,158.5 127.8,158.5 128.4,157.9 128.4,156.9 128.6,156.9 128.6,157.7 128.5,157.8
N$137  (via drill 0.5 pad 1.68)
  other vias: 26.8,161
N$140  (via drill 0.5 pad 1.68)
  other vias: 34.4,161
N$141
  Bottom 1.016: R13.2 103.8,131 103.2,130.4 103.2,112.4 102.2,111.4 101.48,111.4 P3.E
N$142
  Bottom 1.016: 101.2,130.6 101.2,130.8 101,131 R15^.1 101.07,131.32 P3.A
N$143
  Bottom 1.016: P3.S 98.53,115.13 97,113.6 97,105.6 102.6,100 102.6,86.2 101.6,85.2 99.4,85.2 98.2,86.4 98.2,89.4 99.6,90.8 99.6,98.6 97.9,100.3 | 97.9,100.3 97.6,100.6 | LM723.4 92.7,118.5 93.8,117.4 93.8,104.4 97.9,100.3
N$144  (via drill 0.6 pad 2.18)
  other vias: 103.8,139.2
N$145  (via drill 0.6 pad 2.18)
  other vias: 103.8,131.4
N$146  (via drill 0.6 pad 2.18)
  other vias: 101,131.4
N$147  (via drill 0.6 pad 2.18)
  other vias: 101,139.2
N$148  (via drill 0.6 pad 3.81)
  other vias: 114.2,161.2
N$149  (via drill 0.6 pad 3.81)
  other vias: 114.2,151.2
N$150  (via drill 0.6 pad 1.78)
  Top 0.254: v152.6,39 v140.8,39
  Bottom 0.813: U1.11 146,47.48 146,46.2 152.4,39.8 152.4,39.2 v152.6,39 | v140.8,39 135.15,39 STER..14
N$152  (via drill 0.5 pad 1.78)
  other vias: 121.8,28
N$157  (via drill 0.6 pad 1.78)  (1 unrouted)
  Top 0.254: 153.6,37 v142.2,37
  Bottom 0.813: U1.12 148.43,45.97 154.6,39.8 154.6,38 153.6,37 | v142.2,37 133.4,37 131.68,38.72 STER..12
N$161
  Bottom 0.813: R3*.1 121.8,27.6 121,26.8 121,23.79 T3*.C 121.06,23.34 121,23.28 121,22.4 123.4,20 133.6,20 138.95,25.35 PIEZO1.-
N$162
  Bottom 0.813: R4*.2 114.2,47.29 114.2,47 112,44.8 112,37.4 117,32.4 125.6,32.4 127.4,30.6 127.4,27.6 130.9,24.1 T2*.B
N$166  (via drill 0.6 pad 1.78)
  other vias: 124.6,60.8
N$176
  Bottom 0.813: R7*.2 112,47.49 112,46.8 110.6,45.4 110.6,36.8 116.4,31 122.4,31 123.6,29.8 T3*.B
N$177  (via drill 0.6 pad 1.78)
  other vias: 156.2,55.2
N$178  (via drill 0.6 pad 1.78)
  other vias: 156.2,47.6
N$179
  Bottom 0.813: R5*.2 116.4,47.09 116.4,47 113.4,44 113.4,38 117.6,33.8 127.6,33.8 130.2,31.2 T1*.B
N$180
  Bottom 0.813: T2*.C 128.2,23.89 128.2,24.8 125.5,27.5 R2*.1
N$182
  Bottom 0.813: R1*.1 130.37,28.66 T1*.C
N$183
  Bottom 0.813: STER..4 121.8,39.65 R3*.2
N$185  (via drill 0.6 pad 1.78)
  Top 0.254: v132.4,68.2 v122,68.2
  Bottom 1.016: R7*.1 112.1,55.7 112.4,56 112.4,66.6 114,68.2 v122,68.2 | U1.18 145.89,62.11 139.8,68.2 v132.4,68.2
N$186  (via drill 0.6 pad 1.78)
  Top 0.254: v132.2,64.8 v124.8,64.8
  Bottom 0.61: R5*.1 117,55.31 117,54.4 116.4,53.8 108.6,53.8 107.8,54.6 107.8,56 108.4,56.6 108.4,57.4
  Bottom 0.813: R5*.1 116.8,55.31
  Bottom 1.016: R4.1 108,161.6 107.2,162.4 103.9,162.4 100.4,158.9 91.5,158.9 86.5,153.9 86.5,148.8 84.2,146.5 78,146.5 75.1,149.4 75.1,156.7 80.2,161.8 80.2,163.6 79.3,164.5 76.9,164.5 72.3,159.9 51.7,159.9 41.8,150 31.3,150 24.1,142.8 24.1,108.9 34.4,98.6 80.9,98.6 84.3,95.1 108.4,71 108.4,57.4 | U1.19 143.35,61.85 139,66.2 133.2,66.2 132.2,65.2 v132.2,64.8 | 117,55.31 117,63.4 118.4,64.8 v124.8,64.8
N$187
  Bottom 0.813: WYS..3 132.2,11.33 132.2,15.6 130.6,17.2 122.2,17.2 116.4,23 113.86,23 P1*.S
N$188  (via drill 0.5 pad 1.78)
  Bottom 0.813: R1*.2 126.6,38.51 v126.6,39.9 STER..8
N$189
  Bottom 0.813: 136.9,156.8 136.5,156.8 135.8,156.1 134.8,156.1 133.9,157 133.9,158.7 134.7,159.5 136.9,159.5
N$190  (via drill 0.6 pad 1.78)  (1 unrouted)
  Top 0.254: v156,35.2 148.2,35.2
  Bottom 0.813: WYS..6 129.6,6.8 130.2,6.2 135.8,6.2 138.6,9 138.6,15.2 143.8,20.4 151.2,20.4 154.2,23.4 154.2,30 149,35.2 148.4,35.2 148,35.2 | U1.13 150.97,45.63 156,40.6 v156,35.2
N$191  (via drill 0.6 pad 1.78)
  other vias: 135.1,71.9
N$192  (via drill 0.6 pad 1.78)
  Bottom 0.813: R6*.1 v118.4,35.6 117.8,35.6 115,38.4 115,43.2 117.4,45.6 120,45.6 120.6,46.2 120.6,47.48 U1.1 120.4,46.7
N$193
  Bottom 0.61: U1.27 123.03,51.43 122.2,50.6 110,50.6 107.8,48.4
  Bottom 0.813: WYS..5 129.6,12 127.2,14.4 121,14.4 115.8,19.6 110.2,19.6 107.8,22 107.8,48.4
N$194  (via drill 0.6 pad 1.78)
  Top 0.254: v145.2,44.2 v140.8,44.2
  Bottom 0.813: WYS..10 124.6,7.85 124.6,6.2 127.4,3.4 137,3.4 141.4,7.8 141.4,14 145,17.6 152,17.6 157,22.6 157,31 150.2,37.8 150.2,39.6 145.6,44.2 v145.2,44.2 | U1.9 v140.81,44.21 v140.8,44.2
N$195
  Bottom 0.813: WYS..8 127.2,7.79 127.2,6.4 128.8,4.8 136.4,4.8 140,8.4 140,14.6 144.4,19 151.6,19 155.6,23 155.6,30.4 148.8,37.2 148.8,38.8 145.4,42.2 144.4,42.2 143.35,43.25 U1.10
N$196  (via drill 0.6 pad 1.78)
  Bottom 0.61: U1.28 120.49,52.29 119.8,51.6 109.4,51.6 106.4,48.6 106.4,48.4
  Bottom 0.813: WYS..7 v127.06,10.48 127.06,11.54 125.6,13 120.4,13 115.2,18.2 109.6,18.2 106.4,21.4 106.4,48.4
N$197
  Bottom 0.813: WYS..9 123.47,10.47 122.4,9.4 122.4,6.4 126.8,2 137.6,2 142.8,7.2 142.8,13.4 145.6,16.2 152.6,16.2 158.4,22 158.4,40.4 153.51,45.29 U1.14
N$199  (via drill 0.6 pad 2.54)
  Bottom 1.016: 88.3,144.4 91.6,144.4 92.2,145 92.2,155.1 89.9,155.1 88.1,153.3 88.1,145.4 88.3,145.2 v91.4,145.2 91.4,154.1 91.3,154.2 90,154.2 88.7,152.9 88.7,147.2 90,145.9 90.7,145.9 90.7,153.4 90.3,153.4 89.6,152.7 89.6,147.3 89.4,147.1 89.7,147.1 90,146.8 90,152.3 90.1,152.4
N$200  (via drill 0.5 pad 3.81)
  other vias: 14.8,190.1
N$201  (via drill 0.5 pad 3.81)
  other vias: 14.8,185.1
N$202  (via drill 0.5 pad 3.81)
  other vias: 14.8,179.9
N$203  (via drill 0.5 pad 3.81)
  other vias: 14.8,174.9
N$204  (via drill 0.5 pad 3.81)
  other vias: 14.8,169.7
N$205  (via drill 0.5 pad 3.81)
  other vias: 14.8,164.7
N$206  (via drill 0.5 pad 3.81)
  other vias: 26.8,186.4
N$207  (via drill 0.5 pad 3.81)
  other vias: 34.4,186.4
N$208  (via drill 0.5 pad 3.81)
  other vias: 26.8,181.3
N$209  (via drill 0.5 pad 3.81)
  other vias: 34.4,181.3
N$210  (via drill 0.5 pad 3.81)
  other vias: 26.8,176.2
N$211  (via drill 0.5 pad 3.81)
  other vias: 34.4,176.2
N$212  (via drill 0.5 pad 3.81)
  other vias: 51.2,183
N$213  (via drill 0.5 pad 3.81)
  other vias: 69.3,183
N$214  (via drill 0.5 pad 3.81)
  other vias: 69.3,171.6
N$215  (via drill 0.5 pad 3.81)
  other vias: 51.2,164.9
N$216  (via drill 0.5 pad 3.81)
  other vias: 115.2,195.8
N$217  (via drill 0.5 pad 3.81)
  other vias: 130.4,195.8
N$218  (via drill 0.5 pad 3.81)
  other vias: 135.5,195.8
N$219  (via drill 0.5 pad 3.81)
  other vias: 130.4,188.2
N$220  (via drill 0.5 pad 3.81)
  other vias: 135.5,188.2
N$221  (via drill 0.5 pad 3.81)
  other vias: 140.6,195.8
N$222  (via drill 0.5 pad 3.81)
  other vias: 140.6,188.2
N$223  (via drill 0.5 pad 3.81)
  other vias: 153,161.5
N$224  (via drill 0.5 pad 3.81)
  other vias: 152.97,156.49
N$225  (via drill 0.5 pad 3.81)
  other vias: 153,151.49
N$226  (via drill 0.5 pad 3.81)
  other vias: 152.98,128.99
N$227  (via drill 0.5 pad 3.81)
  other vias: 153.03,124.02
N$228  (via drill 0.5 pad 3.81)
  other vias: 91.21,184.53
N$229  (via drill 0.5 pad 3.81)
  other vias: 91.2,165.52
N$230  (via drill 0.5 pad 3.81)
  other vias: 98.84,184.55
N$231  (via drill 0.5 pad 3.81)
  other vias: 14.81,159.61
N$232  (via drill 0.5 pad 3.81)
  other vias: 14.76,154.59
N$233  (via drill 0.5 pad 1.78)
  other vias: 125.5,28
N$235  (via drill 0.6 pad 2.18)
  other vias: 117.4,129.4
N$237  (via drill 0.5 pad 1.78)
  other vias: 121.8,35.6
N$241  (via drill 0.5 pad 1.78)
  other vias: 125.5,35.6
N$248
  Bottom 3.81: 98.8,197 103.2,201.4
N$249
  Bottom 3.81: 85.2,194 85.2,195.4 82.4,198.2
N$250
  Bottom 3.81: 76.2,181.2 85.4,181.2
N$251
  Bottom 1.93: 83.8,180.6 83.8,180.4 85.6,178.6
N$252
  Bottom 0.813: 140.6,121.6 143.6,121.6 | 140.6,121.6 140,121.6 | 140.6,121.6 142,123 142,122.4 141.8,122.2
N$253
  Bottom 1.016: 139,120.8 144.8,120.8
N$257  (via drill 0.5 pad 1.78)
  other vias: 129.6,27.9
N$259
  Top 0.813: W1.3 94.27,6.51 89.85,10.93 87.45,10.93 86.25,9.73 86.25,8.87 SV2.3
N$260
  Top 0.813: W1.4 94.33,9.05 90.85,12.53 84.85,12.53 83.85,11.53 83.85,8.91 SV2.5
N$261
  Top 0.813: W1.6 83.45,14.13 81.22,11.9 SV2.7
N$262
  Top 0.813: SV2.9 78.68,11.76 82.65,15.73 91.45,15.73 93.45,17.73 93.45,25.73 94.65,26.93 96.49,26.93 W1.11
N$263  (via drill 0.6 pad 1.93)
  Top 0.813: SV2.10 v78.67,6.28 77.7,6.28 76.65,7.33 76.65,12.13 81.85,17.33 90.85,17.33 92.05,18.53 92.05,27.33 94.05,29.33 96.55,29.33 W1.12
N$264
  Top 0.813: SV2.8 81.22,5.5 80.05,4.33 77.65,4.33 75.25,6.73 75.25,13.13 80.85,18.73 89.85,18.73 90.65,19.53 90.65,28.93 93.65,31.93 96.57,31.93 W1.13
N$265
  Top 0.813: SV2.6 83.76,5.64 81.05,2.93 76.85,2.93 73.85,5.93 73.85,14.13 80.05,20.33 88.45,20.33 89.25,21.13 89.25,32.13 91.65,34.53 96.51,34.53 W1.14
N$266  (via drill 0.6 pad 1.93)
  other vias: 88.86,6.31
N$267  (via drill 0.6 pad 1.93)
  other vias: 88.86,8.84
N$269  (via drill 0.6 pad 1.93)
  other vias: 86.3,6.33
N$270  (via drill 0.6 pad 1.93)
  other vias: 86.3,8.81
N$271  (via drill 0.6 pad 1.78)
  other vias: 116.9,47.6
N$272  (via drill 0.6 pad 1.93)
  other vias: 83.72,6.33
N$273  (via drill 0.6 pad 1.93)
  other vias: 83.75,8.84
N$274  (via drill 0.6 pad 1.93)
  other vias: 81.22,6.29
N$275  (via drill 0.6 pad 1.93)
  other vias: 81.23,8.83
N$276  (via drill 0.6 pad 1.93)
  other vias: 78.67,8.81
N$277  (via drill 0.5 pad 1.78)
  other vias: 11.13,11.28
N$278  (3 unrouted)
  Top 0.61: 21.29,24.68 21.19,24.58 16.33,24.58 15.33,23.58 15.33,18.78 13.63,17.08 13.63,15.08 12.25,13.8 SV4.11
  Top 0.813: S9.1 S12.2 | S6.1 21.29,24.68 S9.2
N$279  (via drill 0.5 pad 1.78)
  other vias: 8.63,11.28
N$280
  Top 0.61: SV4.12 8.05,13.8 7.03,12.78 7.03,10.38 9.13,8.28 16.73,8.28
  Top 0.813: S3.4 55.47,7.14 55.53,7.08 | 16.73,7.08 29.33,7.08 | 29.33,7.08 29.53,7.08 | 29.53,7.08 42.33,7.08 | 42.33,7.08 55.53,7.08 | 16.73,7.08 16.73,8.28 16.73,10.16 S12.4 | S11.4 29.47,7.14 29.53,7.08 | S10.4 42.47,7.22 42.33,7.08 | S3.3 55.47,7.02 55.53,7.08 | S12.3 16.77,7.04 16.73,7.08 | S11.3 29.47,6.94 29.33,7.08 | S10.3 42.47,6.94 42.33,7.08
N$281  (via drill 0.5 pad 1.78)
  other vias: 11.13,13.78
N$282  (1 unrouted)
  Top 0.61: S9.3 16.71,15.56 16.73,15.54 16.73,13.18 12.93,9.38 9.53,9.38 8.56,10.35 SV4.14
  Top 0.813: 55.53,19.28 55.47,19.34 S2.4 55.47,18.94 55.53,18.88 | 29.73,18.88 29.53,18.88 29.47,18.94 S8.4 | 29.73,18.88 42.13,18.88 | 42.13,18.88 42.53,18.88 | 42.53,18.88 55.53,18.88 | S9.4 16.73,22.02 | S7.4 42.47,18.94 42.53,18.88 | S2.3 55.47,18.82 55.53,18.88 | S7.3 42.47,18.54 42.13,18.88 | 29.53,18.68 29.73,18.88 | S8.3 29.47,18.62 29.53,18.68 | 29.53,18.68 24.13,18.68 23.33,17.88 18.13,17.88 16.77,16.52 S9.3
N$283
  Top 0.61: 23.93,30.88 23.93,20.68 22.33,19.08 17.23,19.08 14.83,16.68 14.83,13.38 12.71,11.26 SV4.13
  Top 0.813: S1.4 55.57,30.92 55.53,30.88 | 16.73,30.88 23.93,30.88 29.13,30.88 | 29.13,30.88 29.73,30.88 | 29.73,30.88 42.53,30.88 | 42.53,30.88 55.53,30.88 | 16.73,30.88 16.73,33.98 S6.4 | S5.4 29.47,31.22 29.13,30.88 | S4.4 42.47,30.94 42.53,30.88 | S1.3 55.47,30.82 55.53,30.88 | S4.3 42.47,30.82 42.53,30.88 | S5.3 29.47,30.62 29.73,30.88 | S6.3 16.77,30.84 16.73,30.88
N$284  (3 unrouted)
  Top 0.406: S5.2 34.03,34.04
  Top 0.61: S5.2 31.51,36.48 15.63,36.48 14.23,35.08 14.23,19.28 11.29,16.34 SV4.9
  Top 0.813: S8.1 S11.2 | S5.1 S8.2
N$285  (via drill 0.5 pad 1.78)
  other vias: 8.53,13.78
N$286
  Top 0.813: 99.29,24.17 99.29,38.54 98.2,39.63 96.69,39.63 W1.16 | 99.29,24.17 99.29,21.68 | 99.29,21.68 99.29,19.18 | 99.29,19.18 99.29,16.9 | 99.29,16.9 99.29,11.54 | 99.29,11.54 99.29,2.16 98.56,1.43 W1.1 90.15,1.43 88.85,2.73 88.85,4.07 SV2.2 | W1.5 99.24,11.59 99.29,11.54 | W1.7 99.06,16.67 99.29,16.9 | W1.8 99.26,19.21 99.29,19.18 | W1.9 99.22,21.75 99.29,21.68 | W1.10 99.17,24.29 99.29,24.17
N$287  (3 unrouted)
  Top 0.61: S4.2 43.59,37.48 15.13,37.48 13.33,35.68 13.33,20.18 11.93,18.88 SV4.7
  Top 0.813: S7.1 S10.2 | S4.1 S7.2
N$288  (via drill 0.5 pad 1.78)
  other vias: 11.13,16.28
N$289
  Top 0.61: S1.1 S1.2 55.56,38.48 14.53,38.48 12.33,36.28 12.33,22.28 11.53,21.48 11.16,21.48 SV4.5
  Top 0.813: S1.1 S2.2 S2.1 S3.2 S3.1
N$290  (via drill 0.5 pad 1.78)
  other vias: 8.63,16.28
N$291  (via drill 0.6 pad 1.93)
  other vias: 5.78,30.68
N$292  (via drill 0.6 pad 1.93)
  other vias: 3.22,30.71
N$293  (via drill 0.6 pad 1.93)
  other vias: 5.73,18.88
N$294  (via drill 0.6 pad 1.93)
  other vias: 5.73,6.78
N$295  (via drill 0.6 pad 1.93)
  other vias: 3.13,6.78
N$303  (via drill 0.5 pad 1.78)
  other vias: 11.03,18.88
N$304  (via drill 0.5 pad 1.78)
  other vias: 8.53,18.88
N$305  (via drill 0.5 pad 1.78)
  other vias: 11.13,21.38
N$306  (via drill 0.5 pad 1.78)
  other vias: 8.53,21.38
N$307  (via drill 0.5 pad 1.78)
  other vias: 8.53,23.98
N$310  (via drill 0.5 pad 1.78)
  other vias: 8.53,26.48
N$311
  Top 0.813: SV4.10 8.4,16.18 8.13,16.18 5.66,13.71 LED3.A 5.73,7.19 5.73,5.98 4.63,4.88 2.33,4.88 1.13,6.08 1.13,16.81 LED2.A 3.22,31.18 LED1.A
N$312
  Top 0.813: SV4.8 3.12,13.44 LED3.K
N$313  (via drill 0.6 pad 1.93)
  other vias: 3.13,18.88
N$316  (via drill 0.6 pad 1.78)
  other vias: 116.9,55.3
N$317  (via drill 0.6 pad 1.78)
  other vias: 114.5,55.3
N$318  (via drill 0.6 pad 1.78)
  other vias: 114.5,47.6
N$319  (via drill 0.6 pad 1.78)
  other vias: 112.1,55.3
N$320  (via drill 0.6 pad 1.78)
  other vias: 112.1,47.6
N$321  (via drill 0.6 pad 1.78)
  other vias: 118.4,28
N$328  (via drill 0.6 pad 1.78)
  other vias: 142.7,71.9
N$329  (via drill 0.6 pad 1.78)
  other vias: 109.6,47.6
N$330  (via drill 0.6 pad 1.78)
  other vias: 132.2,60.8
N$331  (via drill 0.6 pad 1.78)
  other vias: 134.6,62
N$332  (via drill 0.6 pad 1.78)
  other vias: 153.6,37
N$333  (via drill 0.6 pad 1.78)
  other vias: 139.8,58.8
N$334
  Bottom 0.813: 135.5,157.7 135.5,157.2 | 135.5,157.7 135.5,157.8 | 135.5,157.8 135.5,158 | 135.5,157.8 135.4,157.7 135.4,157.4 135.3,157.3 135.3,157.5 135.5,157.7
N$335  (via drill 0.6 pad 1.78)
  other vias: 124.53,10.48
N$336  (via drill 0.6 pad 1.78)
  other vias: 124.51,7.92
N$337  (via drill 0.6 pad 1.78)
  other vias: 127.07,7.93
N$338  (via drill 0.6 pad 1.78)
  other vias: 129.62,10.49
N$339  (via drill 0.6 pad 1.78)
  other vias: 129.62,7.96
N$340  (via drill 0.6 pad 1.78)
  other vias: 132.16,7.94
N$341  (via drill 0.6 pad 1.78)
  other vias: 132.15,10.47
N$342  (via drill 0.6 pad 1.78)
  other vias: 134.69,10.49
N$343  (via drill 0.6 pad 1.78)
  other vias: 134.69,7.94
N$344  (via drill 0.6 pad 1.78)
  other vias: 148.2,35.2
N$346  (via drill 0.6 pad 6.45)
  other vias: 10.25,3.94
N$354
  Bottom 0.61: U1.25 128.11,53.09 130.3,50.9 156.3,50.9 159.6,54.2 159.6,55.6
  Bottom 0.813: 152.2,165.4 150.4,163.6 129.6,163.6 124.2,158.2 124.2,154.6 130.6,148.2 139.8,148.2 145,143 145,123 149.2,118.8 157.4,118.8 159.6,116.6 159.6,55.6
  Bottom 1.016: P4.S 152.47,165.67 152.2,165.4 151.9,165.1
N$357
  Bottom 1.016: R6.2 136.69,82.29 138.8,84.4 154.4,84.4 156.6,82.4 156.6,58.6 155.8,57.8 154.4,57.8 153.6,57 153.6,55.3 U1.15
N$358  (via drill 0.6 pad 1.78)
  Top 0.254: v132.4,71.8 v121.8,71.8
  Bottom 1.016: R14.2 110.2,122.4 108,120.2 108,101.4 105.8,99.2 105.8,80.4 114.4,71.8 v121.8,71.8 | v132.4,71.8 132.4,71 133.4,70 139.4,70 140.2,70.8 140.2,72.8 141.2,73.8 143.8,73.8 144.8,72.8 150.2,72.8 152.4,70.6 152.4,65.8 151,64.4 151,55.24 U1.16
N$359
  Bottom 0.254: 0,95.2 78.8,95.2 104.2,69.8 104.2,0.4
N$360  (via drill 0.5 pad 1.78)
  other vias: 129.6,35.5
N$361  (via drill 0.5 pad 1.78)
  other vias: 134.2,39.9
N$362
  Bottom 0.813: R2*.2 124.06,37.05 STER..6
N$363  (via drill 0.5 pad 1.78)
  other vias: 134.2,42.5
N$364  (via drill 0.5 pad 1.78)
  other vias: 131.7,42.5
N$365  (via drill 0.5 pad 1.78)
  other vias: 131.7,39.9
N$366  (via drill 0.5 pad 1.78)
  other vias: 129.1,42.5
N$367  (via drill 0.5 pad 1.78)
  other vias: 129.1,39.9
N$368  (via drill 0.5 pad 1.78)
  other vias: 126.6,42.4
N$369  (via drill 0.5 pad 1.78)
  other vias: 124.1,39.9
N$370  (via drill 0.5 pad 1.78)
  other vias: 124.1,42.5
N$371  (via drill 0.5 pad 1.78)
  other vias: 121.5,42.5
N$372  (via drill 0.5 pad 1.78)
  other vias: 121.5,39.9
N$373  (via drill 0.5 pad 1.78)
  other vias: 119,39.9
N$374  (via drill 0.5 pad 1.78)
  other vias: 119,42.5
N$375
  Top 0.813: SV4.6 8.52,21.38 6.83,21.38 5.76,20.31 LED2.K
N$376
  Top 0.813: SV4.4 8.54,23.98 7.13,23.98 5.78,25.33 LED1.K
N$378
  Bottom 0.813: 150.8,25.2 150.8,24.4 150.6,24.2 150.2,24.2 149.6,24.8
N$379  (via drill 0.5 pad 6.45)
  other vias: 74.8,104.8
N$380
  Bottom 2.54: 15.1,159.5 15.2,159.4 15.9,159.4 19.1,156.2 19.1,119.8 12.9,113.6 8.3,113.6
N$381
  Bottom 2.54: 8.3,152 8.3,138.5 | 8.3,152 8.3,156.7 10.5,154.5 10.5,154.2 8.3,152
N$383  (via drill 0.8 pad 6.45)
  other vias: 148,68.6
N$384
  Bottom 0.813: 78,102.2 arc258 71.6,102.2
N$385
  Bottom 0.813: 66,102 71.8,102 71.2,102.6 66.2,102.6
N$386
  Bottom 0.813: 82,102 77.8,102
T6  (via drill 0.5 pad 3.81, 0.6 pad 2.54)
  Bottom 1.016: 98.81,175 102.2,175 | 102.2,175 102.3,175 | 102.3,175 T3.2 | 102.3,175 99.7,177.6 99.7,172.5 102.2,175 | 102.2,175 101.5,175 100.9,175.6 100.9,174.2 100.8,174.1
  Bottom 1.27: 75,180 75,178 74,177 77,177 | 77,177 77,178 | 75,180 75,179 77,177 | 77,177 77.79,177 R11.1 | 75,180 75.2,180 75.4,180 78.2,177.2 | 78.2,177.2 78.4,177 78,177 | 78,177 77.8,177 | 78.2,177.2 78,177 | 78.2,177.2 v78,177.2
  Bottom 1.93: 75.2,180 75.6,180 77.8,177.8 77.8,178.2 79.6,180
  Bottom 2.54: 86,202 C10.1
  Bottom 3.81: C4.+ v98.81,165.52 98.81,175 C3.+ 98.81,200.69 98.5,201 98.5,202 | B1.+ 69.31,174.31 75,180 75,199 78,202 86,202 98.5,202 | T5.2 157,129 158,130 158,156.5 | 158,156.5 T6.2 | 75.2,180 75.2,180.6 77.6,183 83.8,183 85.4,181.4 85.4,187.4 87.8,189.8 94.6,189.8 | 94.6,189.8 98.4,189.8 98.6,189.6 98.6,197 96.4,199.2 96.4,193.2 96,192.8 88.8,192.8 88.4,192.4 88.4,198.6 87.4,199.6 94.6,199.6 94.8,199.4 94.8,196.4 93,194.6 92.8,194.6 91,196.4 91.4,196.4 92.4,197.4 85.8,197.4 83.2,200 79.4,200 77.4,198 77.4,186.8 77.2,186.6 81.8,186.6 82.2,186.2 82.2,187.8 84.6,190.2 84.6,194.6 84.8,194.8 83,194.8 80.8,197 80.8,190.6 79.6,189.4 | 94.6,189.8 96.2,189.8 98.2,187.8 | 158,156.5 158,196.4 152.4,202 98.5,202

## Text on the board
Bottom: KUM 2010.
